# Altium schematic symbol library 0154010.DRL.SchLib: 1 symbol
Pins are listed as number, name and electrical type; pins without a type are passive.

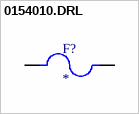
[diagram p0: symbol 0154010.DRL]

## 0154010.DRL
designator F?
10 A 125 V AC 125 V DC Fuse Board Mount (Cartridge Style Excluded) Requires Holder, Surface Mount 2-SMD, Square End Block with Holder; MF: Littelfuse Inc.; MP: 0154010.DRL
footprint FUSE_0154010.DRL
pins: 1, 2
